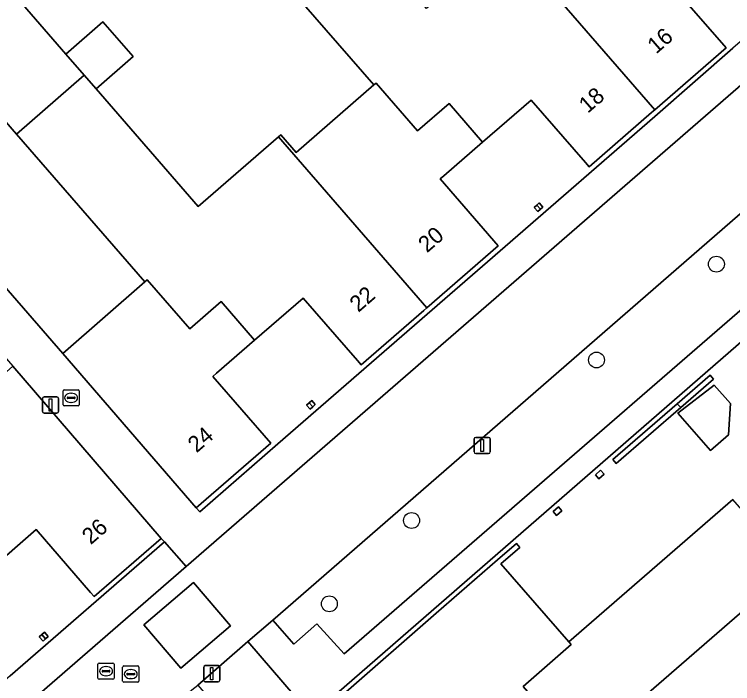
# Model space of a CAD drawing. Extents: x 155887 to 156869, y 383880 to 384678.
# Drawn here: x 156121.25 to 156165.47, y 384059.06 to 384100.28 of the extents above; entities that cross this region are included whole.
import ezdxf

# ---------------------------------------------------------------- set-up
doc = ezdxf.new("R2010")
doc.units = 0
for name, color, linetype in [('IMGEO_Boom', 7, 'Continuous'), ('IMGEO_Erf', 7, 'Continuous'), ('IMGEO_Groenvoorziening', 7, 'Continuous'), ('IMGEO_Kolk', 7, 'Continuous'), ('IMGEO_Lichtmast', 7, 'Continuous'), ('IMGEO_Pand', 7, 'Continuous'), ('IMGEO_Pand_nummerreeks', 7, 'Continuous'), ('IMGEO_Parkeervlak_open', 7, 'Continuous'), ('IMGEO_Rijbaan_lokaal_gesloten', 7, 'Continuous'), ('IMGEO_Rijbaan_lokaal_open', 7, 'Continuous'), ('IMGEO_Rioolput', 7, 'Continuous'), ('IMGEO_Voetpad_open', 7, 'Continuous')]:
    doc.layers.add(name, color=color, linetype=linetype)

msp = doc.modelspace()

# ---------------------------------------------------------------- linework, layer by layer
at = {"layer": 'IMGEO_Boom'}
for centre in [(156164.474, 384084.894), (156157.089, 384078.99), (156145.706, 384069.103), (156140.645, 384063.975)]:
    msp.add_circle(centre, 0.489, dxfattribs=at)
at = {"layer": 'IMGEO_Erf'}
for points in [[(156135.429, 384105.103), (156128.409, 384113.19), (156123.469, 384108.901), (156123.333, 384108.783), (156118.535, 384104.616), (156124.42, 384097.838), (156126.707, 384099.824), (156128.567, 384097.682), (156126.279, 384095.696), (156132.572, 384088.447), (156137.514, 384092.737), (156137.65, 384092.855), (156138.593, 384091.769), (156143.389, 384095.933)], [(156116.35, 384098.695), (156114.296, 384101.058), (156109.272, 384096.625), (156111.284, 384094.307), (156124.224, 384079.401), (156129.291, 384083.805), (156121.378, 384092.91)], [(156201.356, 384069.095), (156193.346, 384078.305), (156189.164, 384083.118), (156185.397, 384087.429), (156180.648, 384092.863), (156141.085, 384058.434), (156145.48, 384053.367), (156153.447, 384044.199), (156157.638, 384039.39), (156173.736, 384020.889), (156173.912, 384020.686), (156188.42, 384033.29), (156189.174, 384033.947), (156196.255, 384040.099), (156197.017, 384040.761), (156213.513, 384055.094), (156213.303, 384055.332), (156205.719, 384064.051)], [(156153.792, 384088.412), (156153.638, 384088.277), (156153.474, 384088.134), (156153.251, 384088.391), (156153.409, 384088.528), (156153.569, 384088.668)], [(156158.309, 384072.612), (156158.099, 384072.853), (156162.062, 384076.297), (156164.085, 384078.055), (156164.295, 384077.814), (156162.281, 384076.064)], [(156162.097, 384075.72), (156164.345, 384077.449), (156165.332, 384076.313), (156165.214, 384074.377), (156164.103, 384073.411)], [(156139.78, 384076.24), (156139.622, 384076.103), (156139.46, 384075.962), (156139.237, 384076.218), (156139.396, 384076.356), (156139.557, 384076.496)], [(156182.458, 384069.069), (156183.568, 384070.034), (156183.45, 384070.17), (156181.363, 384072.571), (156179.277, 384074.972), (156169.389, 384066.381), (156171.186, 384064.314), (156169.256, 384062.637), (156167.459, 384064.704), (156160.156, 384058.358), (156164.447, 384053.419), (156164.565, 384053.283), (156163.455, 384052.319), (156167.627, 384047.518), (156177.743, 384056.308), (156186.748, 384064.132)], [(156157.23, 384071.674), (156157.02, 384071.915), (156157.345, 384072.197), (156157.555, 384071.956)], [(156154.633, 384069.418), (156154.423, 384069.659), (156154.748, 384069.941), (156154.958, 384069.7)], [(156123.102, 384062.219), (156123.333, 384061.966), (156123.176, 384061.822), (156123.016, 384061.676), (156122.784, 384061.929), (156122.943, 384062.074)]]:
    msp.add_lwpolyline(points, close=True, dxfattribs=at)
for points in [[(156161.505, 384102.33), (156165.078, 384098.215), (156160.688, 384094.403), (156160.486, 384094.227), (156156.642, 384090.89), (156156.419, 384091.147), (156153.069, 384095.005), (156150.08, 384092.41), (156147.691, 384090.336), (156147.467, 384090.142), (156151.041, 384086.027), (156146.641, 384082.205), (156146.453, 384082.042), (156142.598, 384078.694), (156142.375, 384078.951), (156139.024, 384082.809), (156136.04, 384080.217), (156133.69, 384078.176), (156133.464, 384077.979), (156137.037, 384073.864), (156132.453, 384069.884), (156132.659, 384069.648), (156137.468, 384073.824), (156146.66, 384081.804), (156151.467, 384085.989), (156160.684, 384093.999), (156165.495, 384098.191)], [(156141.494, 384058.397), (156147.228, 384063.395), (156150.998, 384066.682), (156152.159, 384067.691), (156152.369, 384067.45), (156151.208, 384066.441), (156155.384, 384061.633), (156165.486, 384070.407)], [(156120.993, 384059.536), (156130.502, 384067.788), (156130.296, 384068.003), (156126.155, 384064.42), (156125.931, 384064.679), (156122.589, 384068.541), (156119.606, 384065.948)]]:
    msp.add_lwpolyline(points, dxfattribs=at)
at = {"layer": 'IMGEO_Groenvoorziening'}
msp.add_lwpolyline([(156135.625, 384061.658), (156132.538, 384058.968), (156135.463, 384055.574), (156138.529, 384058.267)], close=True, dxfattribs=at)
at = {"layer": 'IMGEO_Kolk'}
for p, q in [((156124.245, 384076.236), (156124.245, 384077.088)), ((156124.32, 384077.162), (156125.172, 384077.162)), ((156125.246, 384077.088), (156125.246, 384076.236)), ((156124.504, 384076.656), (156124.504, 384076.668)), ((156124.547, 384076.705), (156124.945, 384076.705)), ((156124.733, 384076.942), (156124.758, 384076.942)), ((156124.988, 384076.668), (156124.988, 384076.656)), ((156124.942, 384076.619), (156124.544, 384076.619)), ((156124.756, 384076.382), (156124.731, 384076.382)), ((156125.172, 384076.162), (156124.32, 384076.162))]:
    msp.add_line(p, q, dxfattribs=at)
for points in [[(156124.245, 384076.236), (156124.245, 384077.088)], [(156124.32, 384077.162), (156125.172, 384077.162)], [(156125.246, 384077.088), (156125.246, 384076.236)], [(156125.172, 384076.162), (156124.32, 384076.162)]]:
    msp.add_lwpolyline(points, dxfattribs=at)
for centre, radius, start, end in [((156124.322, 384077.086), 0.0765, 91.552, 178.448), ((156124.322, 384077.086), 0.0765, 91.552, 178.448), ((156125.17, 384077.086), 0.0765, 1.552, 88.448), ((156125.17, 384077.086), 0.0765, 1.552, 88.448), ((156124.544, 384076.665), 0.0403, 85.8775, 175.7526), ((156124.541, 384076.655), 0.0366, 178.938, 274.7102), ((156124.945, 384076.662), 0.043, 264.8664, 352.4533), ((156124.949, 384076.667), 0.0386, 1.7309, 96.639), ((156124.322, 384076.238), 0.0765, 181.552, 268.448), ((156124.322, 384076.238), 0.0765, 181.552, 268.448), ((156125.17, 384076.238), 0.0765, 271.552, 358.448), ((156125.17, 384076.238), 0.0765, 271.552, 358.448)]:
    msp.add_arc(centre, radius, start, end, dxfattribs=at)
for centre, major_axis, ratio, start_param, end_param in [((156124.732, 384076.662), (-0.387, 0.002), 0.722429, 4.712389, 7.853982), ((156124.757, 384076.662), (-0.39, 0.002), 0.717154, 1.570796, 4.712389)]:
    msp.add_ellipse(centre, major_axis=major_axis, ratio=ratio, start_param=start_param, end_param=end_param, dxfattribs=at)
at = {"layer": 'IMGEO_Lichtmast'}
for p, q in [((156123.083, 384076.718), (156123.873, 384076.718)), ((156123.873, 384076.718), (156123.083, 384076.718)), ((156122.983, 384075.818), (156122.983, 384076.618)), ((156122.983, 384076.618), (156122.983, 384075.818)), ((156123.973, 384076.618), (156123.973, 384075.818)), ((156123.973, 384075.818), (156123.973, 384076.618)), ((156123.873, 384075.718), (156123.083, 384075.718)), ((156123.083, 384075.718), (156123.873, 384075.718)), ((156149.555, 384073.325), (156149.555, 384074.125)), ((156149.555, 384074.125), (156149.555, 384073.325)), ((156149.655, 384074.225), (156150.445, 384074.225)), ((156150.445, 384074.225), (156149.655, 384074.225)), ((156150.545, 384074.125), (156150.545, 384073.325)), ((156150.545, 384073.325), (156150.545, 384074.125)), ((156150.445, 384073.225), (156149.655, 384073.225)), ((156149.655, 384073.225), (156150.445, 384073.225)), ((156132.907, 384059.267), (156132.907, 384060.067)), ((156132.907, 384060.067), (156132.907, 384059.267)), ((156133.007, 384060.167), (156133.797, 384060.167)), ((156133.797, 384060.167), (156133.007, 384060.167)), ((156133.897, 384060.067), (156133.897, 384059.267)), ((156133.897, 384059.267), (156133.897, 384060.067)), ((156133.797, 384059.167), (156133.007, 384059.167)), ((156133.007, 384059.167), (156133.797, 384059.167))]:
    msp.add_line(p, q, dxfattribs=at)
for points in [[(156123.403, 384076.593), (156123.553, 384076.593), (156123.553, 384075.843), (156123.403, 384075.843), (156123.403, 384076.593)], [(156149.975, 384074.1), (156150.125, 384074.1), (156150.125, 384073.35), (156149.975, 384073.35), (156149.975, 384074.1)], [(156133.327, 384060.042), (156133.477, 384060.042), (156133.477, 384059.292), (156133.327, 384059.292), (156133.327, 384060.042)]]:
    msp.add_lwpolyline(points, dxfattribs=at)
for centre, start, end in [((156123.083, 384076.618), 90, 180), ((156123.083, 384076.618), 90, 180), ((156123.873, 384076.618), 0, 90), ((156123.873, 384076.618), 360, 90), ((156123.083, 384075.818), 180, 270), ((156123.083, 384075.818), 180, 270), ((156123.873, 384075.818), 270, 0), ((156123.873, 384075.818), 270, 0), ((156149.655, 384074.125), 90, 180), ((156149.655, 384074.125), 90, 180), ((156150.445, 384074.125), 0, 90), ((156150.445, 384074.125), 360, 90), ((156149.655, 384073.325), 180, 270), ((156149.655, 384073.325), 180, 270), ((156150.445, 384073.325), 270, 0), ((156150.445, 384073.325), 270, 0), ((156133.007, 384060.067), 90, 180), ((156133.007, 384060.067), 90, 180), ((156133.797, 384060.067), 0, 90), ((156133.797, 384060.067), 360, 90), ((156133.007, 384059.267), 180, 270), ((156133.007, 384059.267), 180, 270), ((156133.797, 384059.267), 270, 0), ((156133.797, 384059.267), 270, 0)]:
    msp.add_arc(centre, 0.1, start, end, dxfattribs=at)
at = {"layer": 'IMGEO_Pand'}
for points in [[(156118.535, 384104.616), (156117.584, 384105.711), (156117.456, 384105.6), (156114.888, 384108.558), (156112.919, 384106.848), (156110.817, 384109.269), (156107.811, 384106.658), (156104.463, 384110.514), (156104.238, 384110.773), (156100.089, 384107.17), (156109.272, 384096.625), (156114.296, 384101.058), (156116.35, 384098.695), (156121.378, 384092.91), (156125.552, 384096.534), (156124.42, 384097.838)], [(156152.503, 384103.838), (156151.56, 384104.925), (156146.616, 384100.634), (156139.597, 384108.722), (156135.429, 384105.103), (156143.389, 384095.933), (156143.517, 384096.044), (156146.073, 384093.098), (156148.023, 384094.786), (156150.08, 384092.41), (156153.069, 384095.005), (156156.419, 384091.147), (156156.642, 384090.89), (156160.486, 384094.227), (156160.688, 384094.403)], [(156164.101, 384104.595), (156162.034, 384106.965), (156160.115, 384105.291), (156157.565, 384108.232), (156157.437, 384108.121), (156154.56, 384105.623), (156152.639, 384103.956), (156152.503, 384103.838), (156160.688, 384094.403), (156165.078, 384098.215), (156161.505, 384102.33), (156161.73, 384102.527)], [(156124.42, 384097.838), (156125.552, 384096.534), (156126.279, 384095.696), (156128.567, 384097.682), (156126.707, 384099.824)], [(156137.514, 384092.737), (156132.572, 384088.447), (156126.279, 384095.696), (156125.552, 384096.534), (156121.378, 384092.91), (156129.291, 384083.805), (156129.429, 384083.925), (156132.045, 384080.914), (156133.979, 384082.592), (156136.04, 384080.217), (156139.024, 384082.809), (156142.375, 384078.951), (156142.598, 384078.694), (156146.453, 384082.042), (156146.641, 384082.205)], [(156137.514, 384092.737), (156146.641, 384082.205), (156151.041, 384086.027), (156147.467, 384090.142), (156147.691, 384090.336), (156150.08, 384092.41), (156148.023, 384094.786), (156146.073, 384093.098), (156143.517, 384096.044), (156143.389, 384095.933), (156138.593, 384091.769), (156137.65, 384092.855)], [(156153.569, 384088.668), (156153.409, 384088.528), (156153.638, 384088.277), (156153.792, 384088.412)], [(156153.638, 384088.277), (156153.409, 384088.528), (156153.251, 384088.391), (156153.474, 384088.134)], [(156129.291, 384083.805), (156124.224, 384079.401), (156132.453, 384069.884), (156137.037, 384073.864), (156133.464, 384077.979), (156133.69, 384078.176), (156136.04, 384080.217), (156133.979, 384082.592), (156132.045, 384080.914), (156129.429, 384083.925)], [(156121.154, 384078.608), (156116.146, 384074.16), (156110.019, 384081.21), (156109.089, 384082.281), (156104.923, 384078.636), (156112.889, 384069.462), (156113.017, 384069.573), (156115.569, 384066.63), (156117.532, 384068.335), (156119.606, 384065.948), (156122.589, 384068.541), (156125.931, 384064.679), (156126.155, 384064.42), (156130.296, 384068.003)], [(156164.295, 384077.814), (156164.085, 384078.055), (156162.062, 384076.297), (156162.281, 384076.064)], [(156162.097, 384075.72), (156164.103, 384073.411), (156165.214, 384074.377), (156165.332, 384076.313), (156164.345, 384077.449)], [(156139.622, 384076.103), (156139.396, 384076.356), (156139.237, 384076.218), (156139.46, 384075.962)], [(156139.557, 384076.496), (156139.396, 384076.356), (156139.622, 384076.103), (156139.78, 384076.24)], [(156162.281, 384076.064), (156162.062, 384076.297), (156158.099, 384072.853), (156158.309, 384072.612)], [(156157.02, 384071.915), (156157.23, 384071.674), (156157.555, 384071.956), (156157.345, 384072.197)], [(156160.156, 384058.358), (156167.459, 384064.704), (156169.16, 384066.182), (156165.486, 384070.407), (156155.384, 384061.633), (156155.535, 384061.459), (156152.567, 384058.881), (156154.274, 384056.92), (156151.855, 384054.816), (156154.433, 384051.857), (156150.577, 384048.505), (156150.32, 384048.281), (156153.687, 384044.408), (156153.854, 384044.215), (156164.447, 384053.419)], [(156154.958, 384069.7), (156154.748, 384069.941), (156154.423, 384069.659), (156154.633, 384069.418)], [(156151.855, 384054.816), (156154.274, 384056.92), (156152.567, 384058.881), (156155.535, 384061.459), (156155.384, 384061.633), (156151.208, 384066.441), (156152.369, 384067.45), (156152.159, 384067.691), (156150.998, 384066.682), (156147.228, 384063.395), (156141.494, 384058.397), (156145.511, 384053.802), (156149.614, 384057.389), (156149.816, 384057.157)], [(156122.943, 384062.074), (156122.784, 384061.929), (156123.016, 384061.676), (156123.176, 384061.822)], [(156123.102, 384062.219), (156122.943, 384062.074), (156123.176, 384061.822), (156123.333, 384061.966)]]:
    msp.add_lwpolyline(points, close=True, dxfattribs=at)
at = {"layer": 'IMGEO_Parkeervlak_open'}
msp.add_lwpolyline([(156176.542, 384091.235), (156173.637, 384094.684), (156137.163, 384062.975), (156138.447, 384061.477), (156139.875, 384062.731), (156141.565, 384060.898)], close=True, dxfattribs=at)
at = {"layer": 'IMGEO_Rijbaan_lokaal_gesloten'}
for points in [[(156220.023, 384134.972), (156222.856, 384137.431), (156224.147, 384138.552), (156223.837, 384138.892), (156220.134, 384142.954), (156131.822, 384066.268), (156079.811, 384021.104), (156077.481, 384019.012), (156075.96, 384017.712), (156075.644, 384017.414)], [(156082.143, 384015.142), (156083.578, 384016.476), (156087.385, 384019.812), (156128.423, 384055.413), (156131.846, 384058.384), (156132.186, 384058.671), (156132.538, 384058.968), (156135.625, 384061.658), (156137.163, 384062.975), (156173.637, 384094.684), (156176.739, 384097.381), (156179.022, 384099.365), (156180.638, 384100.784), (156183.098, 384102.929), (156185.393, 384104.912), (156190.357, 384109.221), (156220.023, 384134.972)]]:
    msp.add_lwpolyline(points, dxfattribs=at)
msp.add_lwpolyline([(156134.557, 384062.607), (156131.507, 384060.001), (156129.223, 384062.675), (156132.273, 384065.281)], close=True, dxfattribs=at)
at = {"layer": 'IMGEO_Rijbaan_lokaal_open'}
msp.add_lwpolyline([(156131.507, 384060.001), (156134.557, 384062.607), (156132.273, 384065.281), (156129.223, 384062.675)], close=True, dxfattribs=at)
at = {"layer": 'IMGEO_Rioolput'}
for p, q in [((156126.47, 384060.324), (156127.322, 384060.324)), ((156126.395, 384059.398), (156126.395, 384060.25)), ((156126.697, 384059.867), (156127.095, 384059.867)), ((156126.883, 384060.104), (156126.908, 384060.104)), ((156127.396, 384060.25), (156127.396, 384059.398)), ((156127.918, 384059.218), (156127.918, 384060.07)), ((156127.993, 384060.144), (156128.845, 384060.144)), ((156128.406, 384059.924), (156128.431, 384059.924)), ((156128.919, 384060.07), (156128.919, 384059.218)), ((156126.654, 384059.818), (156126.654, 384059.83)), ((156127.092, 384059.781), (156126.694, 384059.781)), ((156126.906, 384059.544), (156126.881, 384059.544)), ((156127.138, 384059.83), (156127.138, 384059.818)), ((156128.177, 384059.638), (156128.177, 384059.65)), ((156128.615, 384059.601), (156128.217, 384059.601)), ((156128.22, 384059.687), (156128.618, 384059.687)), ((156128.661, 384059.65), (156128.661, 384059.638)), ((156127.322, 384059.324), (156126.47, 384059.324)), ((156128.845, 384059.144), (156127.993, 384059.144)), ((156128.429, 384059.364), (156128.404, 384059.364))]:
    msp.add_line(p, q, dxfattribs=at)
for points in [[(156126.47, 384060.324), (156127.322, 384060.324)], [(156126.395, 384059.398), (156126.395, 384060.25)], [(156127.396, 384060.25), (156127.396, 384059.398)], [(156127.918, 384059.218), (156127.918, 384060.07)], [(156127.993, 384060.144), (156128.845, 384060.144)], [(156128.919, 384060.07), (156128.919, 384059.218)], [(156127.322, 384059.324), (156126.47, 384059.324)], [(156128.845, 384059.144), (156127.993, 384059.144)]]:
    msp.add_lwpolyline(points, dxfattribs=at)
for centre, radius, start, end in [((156126.472, 384060.248), 0.0765, 91.552, 178.448), ((156126.472, 384060.248), 0.0765, 91.552, 178.448), ((156127.32, 384060.248), 0.0765, 1.552, 88.448), ((156127.32, 384060.248), 0.0765, 1.552, 88.448), ((156126.694, 384059.827), 0.0403, 85.8775, 175.7526), ((156127.099, 384059.829), 0.0386, 1.7309, 96.639), ((156127.995, 384060.068), 0.0765, 91.552, 178.448), ((156127.995, 384060.068), 0.0765, 91.552, 178.448), ((156128.843, 384060.068), 0.0765, 1.552, 88.448), ((156128.843, 384060.068), 0.0765, 1.552, 88.448), ((156126.472, 384059.4), 0.0765, 181.552, 268.448), ((156126.472, 384059.4), 0.0765, 181.552, 268.448), ((156126.691, 384059.817), 0.0366, 178.938, 274.7102), ((156127.095, 384059.824), 0.043, 264.8664, 352.4533), ((156127.32, 384059.4), 0.0765, 271.552, 358.448), ((156127.32, 384059.4), 0.0765, 271.552, 358.448), ((156128.217, 384059.647), 0.0403, 85.8775, 175.7526), ((156128.214, 384059.637), 0.0366, 178.938, 274.7102), ((156128.618, 384059.644), 0.043, 264.8664, 352.4533), ((156128.622, 384059.649), 0.0386, 1.7309, 96.639), ((156127.995, 384059.22), 0.0765, 181.552, 268.448), ((156127.995, 384059.22), 0.0765, 181.552, 268.448), ((156128.843, 384059.22), 0.0765, 271.552, 358.448), ((156128.843, 384059.22), 0.0765, 271.552, 358.448)]:
    msp.add_arc(centre, radius, start, end, dxfattribs=at)
for centre, major_axis, ratio, start_param, end_param in [((156126.882, 384059.824), (-0.387, 0.002), 0.722429, 4.712389, 7.853982), ((156126.907, 384059.824), (-0.39, 0.002), 0.717154, 1.570796, 4.712389), ((156128.405, 384059.644), (-0.387, 0.002), 0.722429, 4.712389, 7.853982), ((156128.43, 384059.644), (-0.39, 0.002), 0.717154, 1.570796, 4.712389)]:
    msp.add_ellipse(centre, major_axis=major_axis, ratio=ratio, start_param=start_param, end_param=end_param, dxfattribs=at)
at = {"layer": 'IMGEO_Voetpad_open'}
for points in [[(156182.818, 384182.155), (156096.403, 384107.059), (156097.741, 384105.518), (156097.934, 384105.287), (156106.198, 384095.821), (156112.601, 384088.452), (156115.028, 384085.659), (156116.761, 384083.662), (156121.154, 384078.608), (156130.296, 384068.003), (156130.502, 384067.788), (156131.822, 384066.268), (156220.134, 384142.954)], [(156075.644, 384017.414), (156075.96, 384017.712), (156077.481, 384019.012), (156079.811, 384021.104), (156131.822, 384066.268), (156130.502, 384067.788), (156120.993, 384059.536), (156116.175, 384055.356), (156106.978, 384047.376), (156102.161, 384043.195), (156092.905, 384035.164), (156088.272, 384031.12), (156088.111, 384030.979), (156082.073, 384025.755), (156079.199, 384023.268), (156078.852, 384022.966), (156074.654, 384019.297)]]:
    msp.add_lwpolyline(points, dxfattribs=at)
for points in [[(156146.66, 384081.804), (156137.468, 384073.824), (156132.659, 384069.648), (156132.453, 384069.884), (156124.224, 384079.401), (156111.284, 384094.307), (156109.272, 384096.625), (156100.089, 384107.17), (156099.868, 384107.468), (156142.263, 384144.204), (156142.457, 384143.983), (156150.675, 384134.478), (156165.658, 384117.25), (156174.844, 384106.671), (156175.007, 384106.446), (156165.495, 384098.191), (156160.684, 384093.999), (156151.467, 384085.989)], [(156179.022, 384099.365), (156176.739, 384097.381), (156178.027, 384095.89), (156179.682, 384093.931), (156178.181, 384092.657), (156176.542, 384091.235), (156141.565, 384060.898), (156139.875, 384062.731), (156138.447, 384061.477), (156137.163, 384062.975), (156135.625, 384061.658), (156138.529, 384058.267), (156135.463, 384055.574), (156136.441, 384054.434), (156139.553, 384057.119), (156141.085, 384058.434), (156180.648, 384092.863), (156182.946, 384094.858)]]:
    msp.add_lwpolyline(points, close=True, dxfattribs=at)

# ---------------------------------------------------------------- texts
at = {"layer": 'IMGEO_Pand_nummerreeks'}
for s, rotation, p in [('16', 40.9665, (156160.763, 384097.804)), ('18', 40.9665, (156156.547, 384094.144)), ('20', 40.9753, (156146.656, 384085.557)), ('22', 40.9779, (156142.431, 384081.887)), ('24', 40.9657, (156132.469, 384073.236)), ('26', 40.8691, (156125.952, 384067.577))]:
    msp.add_text(s, height=1, rotation=rotation, dxfattribs=at).set_placement(p)

doc.saveas('drawing.dxf')
